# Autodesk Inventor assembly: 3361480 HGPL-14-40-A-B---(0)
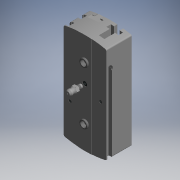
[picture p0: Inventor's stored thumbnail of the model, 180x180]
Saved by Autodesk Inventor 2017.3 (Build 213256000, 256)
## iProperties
Category: PARTsolutions
Company: FESTO
Part Number: 3361480 HGPL-14-40-A-B---(0)
Catalog Web Link: www.cadenas.de
Description: HGPL-B-Parallel gripper
Vendor: FESTO
Document SubType Name: Assembly
Designer: partserver
Manufacturer: FESTO
Mass: 440 g
Surface Area: 512.114 cm^2
Volume: 120.05 cm^3
Density: 3.66514 g/cm^3
Title: 3361480 HGPL-14-40-A-B---(0)
Author: Cadenas PARTsolutions
Comments: Parallel gripper
PSOL_IDENT_0: {ATYP=ASSISTANT},{DATA=script=$CADENAS_DATA/23d-libs/festo/webfesto.vbb/&M_FAMILY=HGPL&M_GROUP=01&M_
PSOL_IDENT_1: PARTNO=3361480&IDCODE1=HGPL-14-40-A-B&IDCODE2=&customer_number_cns=&MATES=1&LOD=HI&LOCKERP=0&SINGLEP
PSOL_IDENT_2: ART=1}
NB: 3361480 HGPL-14-40-A-B---(0)
NN: HGPL-B
NT: Parallel gripper
NBSYN: $TNR. $TYP.---($HUBST.)
LINA: 3361480 HGPL-14-40-A-B---(0)
CATALOG: Festo
TNR: 3361480
TYP: HGPL-14-40-A-B
KDM: 14
HUB: 40
HUBST: 0
L1: 113.6
L2: 60
L3: 0
L4: 102
L5: 22
L6: 8
H1: 30
H2: 29
H3: 24.4
H4: 10
H5: 12
H6: 11.2
H7: 0
H10: 4
B1: 48
B2: 34.5
B3: 22
B4: 40
G3: M3
T6: 6.5
CNSMASSEXACT: 0.44
SUPPLIER: FESTO
ARTICLENO: 3361480 HGPL-14-40-A-B---(0)
BOMINFO: 3361480 HGPL-14-40-A-B---(0)
CREATOR: CADENAS GmbH
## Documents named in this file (8)
- e:\temp\worker_61\temp\exporttempdir_4812_320_CDwH3\format_0\3361480 HGPL-14-40-A-B---(0).iam
- e:\temp\worker_61\temp\exporttempdir_4812_320_CDwH3\format_0\3361863 HGPL-14-40-A-B---(GEH).ipt
- e:\temp\worker_61\temp\exporttempdir_4812_320_CDwH3\format_0\3385160 HGPL-BAC-14-40---(J).ipt
- e:\temp\worker_61\temp\exporttempdir_4812_320_CDwH3\format_0\189652 ZBH-5.ipt
- e:\temp\worker_61\temp\exporttempdir_4812_320_CDwH3\format_0\DIN-913 - M3x3.ipt
- e:\temp\worker_61\temp\exporttempdir_4812_320_CDwH3\format_0\DIN-913 - M5x5.ipt
- e:\temp\worker_61\temp\exporttempdir_4812_320_CDwH3\format_0\DIN-71412 A M5x0_8_SW7.ipt
- e:\temp\worker_61\temp\exporttempdir_4812_320_CDwH3\format_0\150927 ZBH-9.ipt
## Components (14 placed, 7 different names)
1. 3361863 HGPL-14-40-A-B---(GEH):1 — JAW1_Z@1 <-> ANBAU_Z@2, JAW1_YZ@1 <-> ANBAU_YZ@2, PIN_1_XY@1 <-> IP1_XY@8, PIN_1_Z@1 <-> IP1_Z@8, PIN_1_YZ@1 <-> IP1_YZ@8, PIN_2_XY@1 <-> IP1_XY@9, PIN_2_Z@1 <-> IP1_Z@9, PIN_2_YZ@1 <-> IP1_YZ@9, NIPPEL_OBEN_XY@1 <-> IP1_XY@10, NIPPEL_OBEN_Z@1 <-> IP1_Z@10, NIPPEL_OBEN_YZ@1 <-> IP1_YZ@10, NIPPEL_UNTEN_XY@1 <-> IP1_XY@11, NIPPEL_UNTEN_Z@1 <-> IP1_Z@11, NIPPEL_UNTEN_YZ@1 <-> IP1_YZ@11, NIPPEL_XY@1 <-> ANBAU_XY@12, NIPPEL_Z@1 <-> ANBAU_Z@12, NIPPEL_YZ@1 <-> ANBAU_YZ@12, ZBH_UNTEN_1_XY@1 <-> insert_XY@13, ZBH_UNTEN_1_Z@1 <-> insert_Z@13, ZBH_UNTEN_1_YZ@1 <-> insert_YZ@13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
2. 3385160 HGPL-BAC-14-40---(J):1 — JAW1_Z@1 <-> ANBAU_Z@2, JAW1_YZ@1 <-> ANBAU_YZ@2, ZBHJAW1_XY@2 <-> insert_XY@3, ZBHJAW1_Z@2 <-> insert_Z@3, ZBHJAW1_YZ@2 <-> insert_YZ@3, ZBHJAW2_XY@2 <-> insert_XY@4, ZBHJAW2_Z@2 <-> insert_Z@4, ZBHJAW2_YZ@2 <-> insert_YZ@4
3. 189652 ZBH-5:1 — ZBHJAW1_XY@2 <-> insert_XY@3, ZBHJAW1_Z@2 <-> insert_Z@3, ZBHJAW1_YZ@2 <-> insert_YZ@3
4. 189652 ZBH-5:2 — ZBHJAW2_XY@2 <-> insert_XY@4, ZBHJAW2_Z@2 <-> insert_Z@4, ZBHJAW2_YZ@2 <-> insert_YZ@4
5. 3385160 HGPL-BAC-14-40---(J):2 — ZBHJAW1_XY@5 <-> insert_XY@6, ZBHJAW1_Z@5 <-> insert_Z@6, ZBHJAW1_YZ@5 <-> insert_YZ@6, ZBHJAW2_XY@5 <-> insert_XY@7, ZBHJAW2_Z@5 <-> insert_Z@7, ZBHJAW2_YZ@5 <-> insert_YZ@7
6. 189652 ZBH-5:3 — ZBHJAW1_XY@5 <-> insert_XY@6, ZBHJAW1_Z@5 <-> insert_Z@6, ZBHJAW1_YZ@5 <-> insert_YZ@6
7. 189652 ZBH-5:4 — ZBHJAW2_XY@5 <-> insert_XY@7, ZBHJAW2_Z@5 <-> insert_Z@7, ZBHJAW2_YZ@5 <-> insert_YZ@7
8. DIN-913 - M3x3:1 — PIN_1_XY@1 <-> IP1_XY@8, PIN_1_Z@1 <-> IP1_Z@8, PIN_1_YZ@1 <-> IP1_YZ@8
9. DIN-913 - M3x3:2 — PIN_2_XY@1 <-> IP1_XY@9, PIN_2_Z@1 <-> IP1_Z@9, PIN_2_YZ@1 <-> IP1_YZ@9
10. DIN-913 - M5x5:1 — NIPPEL_OBEN_XY@1 <-> IP1_XY@10, NIPPEL_OBEN_Z@1 <-> IP1_Z@10, NIPPEL_OBEN_YZ@1 <-> IP1_YZ@10
11. DIN-913 - M5x5:2 — NIPPEL_UNTEN_XY@1 <-> IP1_XY@11, NIPPEL_UNTEN_Z@1 <-> IP1_Z@11, NIPPEL_UNTEN_YZ@1 <-> IP1_YZ@11
12. DIN-71412 A M5x0_8_SW7:1 — NIPPEL_XY@1 <-> ANBAU_XY@12, NIPPEL_Z@1 <-> ANBAU_Z@12, NIPPEL_YZ@1 <-> ANBAU_YZ@12
13. 150927 ZBH-9:1 — ZBH_UNTEN_1_XY@1 <-> insert_XY@13, ZBH_UNTEN_1_Z@1 <-> insert_Z@13, ZBH_UNTEN_1_YZ@1 <-> insert_YZ@13
14. 150927 ZBH-9:2 — ZBH_UNTEN_2_XY@1 <-> insert_XY@14, ZBH_UNTEN_2_Z@1 <-> insert_Z@14, ZBH_UNTEN_2_YZ@1 <-> insert_YZ@14
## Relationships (35: Mate 21, Angle 12, Flush 2)
- JAW1_Z@1 <-> ANBAU_Z@2 [Mate]: 3361863 HGPL-14-40-A-B---(GEH):1 ↔ 3385160 HGPL-BAC-14-40---(J):1
- JAW1_YZ@1 <-> ANBAU_YZ@2 [Angle]: 3361863 HGPL-14-40-A-B---(GEH):1 ↔ 3385160 HGPL-BAC-14-40---(J):1
- ZBHJAW1_XY@2 <-> insert_XY@3 [Mate]: 3385160 HGPL-BAC-14-40---(J):1 ↔ 189652 ZBH-5:1
- ZBHJAW1_Z@2 <-> insert_Z@3 [Mate]: 3385160 HGPL-BAC-14-40---(J):1 ↔ 189652 ZBH-5:1
- ZBHJAW1_YZ@2 <-> insert_YZ@3 [Angle]: 3385160 HGPL-BAC-14-40---(J):1 ↔ 189652 ZBH-5:1
- ZBHJAW2_XY@2 <-> insert_XY@4 [Mate]: 3385160 HGPL-BAC-14-40---(J):1 ↔ 189652 ZBH-5:2
- ZBHJAW2_Z@2 <-> insert_Z@4 [Mate]: 3385160 HGPL-BAC-14-40---(J):1 ↔ 189652 ZBH-5:2
- ZBHJAW2_YZ@2 <-> insert_YZ@4 [Angle]: 3385160 HGPL-BAC-14-40---(J):1 ↔ 189652 ZBH-5:2
- ZBHJAW1_XY@5 <-> insert_XY@6 [Mate]: 3385160 HGPL-BAC-14-40---(J):2 ↔ 189652 ZBH-5:3
- ZBHJAW1_Z@5 <-> insert_Z@6 [Mate]: 3385160 HGPL-BAC-14-40---(J):2 ↔ 189652 ZBH-5:3
- ZBHJAW1_YZ@5 <-> insert_YZ@6 [Angle]: 3385160 HGPL-BAC-14-40---(J):2 ↔ 189652 ZBH-5:3
- ZBHJAW2_XY@5 <-> insert_XY@7 [Mate]: 3385160 HGPL-BAC-14-40---(J):2 ↔ 189652 ZBH-5:4
- ZBHJAW2_Z@5 <-> insert_Z@7 [Mate]: 3385160 HGPL-BAC-14-40---(J):2 ↔ 189652 ZBH-5:4
- ZBHJAW2_YZ@5 <-> insert_YZ@7 [Angle]: 3385160 HGPL-BAC-14-40---(J):2 ↔ 189652 ZBH-5:4
- PIN_1_XY@1 <-> IP1_XY@8 [Mate]: 3361863 HGPL-14-40-A-B---(GEH):1 ↔ DIN-913 - M3x3:1
- PIN_1_Z@1 <-> IP1_Z@8 [Mate]: 3361863 HGPL-14-40-A-B---(GEH):1 ↔ DIN-913 - M3x3:1
- PIN_1_YZ@1 <-> IP1_YZ@8 [Angle]: 3361863 HGPL-14-40-A-B---(GEH):1 ↔ DIN-913 - M3x3:1
- PIN_2_XY@1 <-> IP1_XY@9 [Mate]: 3361863 HGPL-14-40-A-B---(GEH):1 ↔ DIN-913 - M3x3:2
- PIN_2_Z@1 <-> IP1_Z@9 [Mate]: 3361863 HGPL-14-40-A-B---(GEH):1 ↔ DIN-913 - M3x3:2
- PIN_2_YZ@1 <-> IP1_YZ@9 [Angle]: 3361863 HGPL-14-40-A-B---(GEH):1 ↔ DIN-913 - M3x3:2
- NIPPEL_OBEN_XY@1 <-> IP1_XY@10 [Flush]: 3361863 HGPL-14-40-A-B---(GEH):1 ↔ DIN-913 - M5x5:1
- NIPPEL_OBEN_Z@1 <-> IP1_Z@10 [Mate]: 3361863 HGPL-14-40-A-B---(GEH):1 ↔ DIN-913 - M5x5:1
- NIPPEL_OBEN_YZ@1 <-> IP1_YZ@10 [Angle]: 3361863 HGPL-14-40-A-B---(GEH):1 ↔ DIN-913 - M5x5:1
- NIPPEL_UNTEN_XY@1 <-> IP1_XY@11 [Flush]: 3361863 HGPL-14-40-A-B---(GEH):1 ↔ DIN-913 - M5x5:2
- NIPPEL_UNTEN_Z@1 <-> IP1_Z@11 [Mate]: 3361863 HGPL-14-40-A-B---(GEH):1 ↔ DIN-913 - M5x5:2
- NIPPEL_UNTEN_YZ@1 <-> IP1_YZ@11 [Angle]: 3361863 HGPL-14-40-A-B---(GEH):1 ↔ DIN-913 - M5x5:2
- NIPPEL_XY@1 <-> ANBAU_XY@12 [Mate]: 3361863 HGPL-14-40-A-B---(GEH):1 ↔ DIN-71412 A M5x0_8_SW7:1
- NIPPEL_Z@1 <-> ANBAU_Z@12 [Mate]: 3361863 HGPL-14-40-A-B---(GEH):1 ↔ DIN-71412 A M5x0_8_SW7:1
- NIPPEL_YZ@1 <-> ANBAU_YZ@12 [Angle]: 3361863 HGPL-14-40-A-B---(GEH):1 ↔ DIN-71412 A M5x0_8_SW7:1
- ZBH_UNTEN_1_XY@1 <-> insert_XY@13 [Mate]: 3361863 HGPL-14-40-A-B---(GEH):1 ↔ 150927 ZBH-9:1
- ZBH_UNTEN_1_Z@1 <-> insert_Z@13 [Mate]: 3361863 HGPL-14-40-A-B---(GEH):1 ↔ 150927 ZBH-9:1
- ZBH_UNTEN_1_YZ@1 <-> insert_YZ@13 [Angle]: 3361863 HGPL-14-40-A-B---(GEH):1 ↔ 150927 ZBH-9:1
- ZBH_UNTEN_2_XY@1 <-> insert_XY@14 [Mate]: 3361863 HGPL-14-40-A-B---(GEH):1 ↔ 150927 ZBH-9:2
- ZBH_UNTEN_2_Z@1 <-> insert_Z@14 [Mate]: 3361863 HGPL-14-40-A-B---(GEH):1 ↔ 150927 ZBH-9:2
- ZBH_UNTEN_2_YZ@1 <-> insert_YZ@14 [Angle]: 3361863 HGPL-14-40-A-B---(GEH):1 ↔ 150927 ZBH-9:2
